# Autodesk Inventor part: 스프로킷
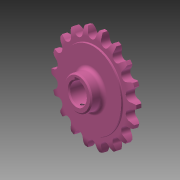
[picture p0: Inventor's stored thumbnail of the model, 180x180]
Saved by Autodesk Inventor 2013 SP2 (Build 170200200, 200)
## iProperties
Created: 2016-03
Part Number: 스프로킷
Material: 강철, 탄소
Document SubType Name: Modeling
Designer: mduedu
Density: 7.87 g/cm^3
Mass: 301.818 g
Surface Area: 124.882 cm^2
Volume: 38.3505 cm^3
Author: mduedu
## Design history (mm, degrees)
sketch "스케치1"
  geometry: L1 (0, 5)-(29.5, 5); L2 (29.5, 5)-(29.5, 4.1); L3 (30, 3.6)-(33.625, 3.6); L4 (40, 2)-(40, 0); L5 (40, 0)-(0, 0); L6 (0, 0)-(0, 5); L7 (0, -5)-(29.5, -5); L8 (29.5, -5)-(29.5, -4.1); L9 (30, -3.6)-(33.625, -3.6); L10 (40, -2)-(40, 0); L11 (0, 0)-(0, -5); A1 r 13.5 centre (33.625, -9.9) between (40, 2) and (33.625, 3.6); A2 r 13.5 centre (33.625, 9.9) between (33.625, -3.6) and (40, -2); A3 r 0.5 centre (30, 4.1) between (29.5, 4.1) and (30, 3.6); A4 r 0.5 centre (30, -4.1) between (30, -3.6) and (29.5, -4.1); 2 further points
  constraints: 22 end point, 8 point on circle, 6 symmetric about line, 5 tangent, 4 centre point, 4 parallel, 4 point on line, 1 equal radius, 1 horizontal, 1 perpendicular, 1 other
  dimensions: "d0" = 80 diameter of L4 L6; "d2" = 59 diameter of L2 L6; "d3" = 1.6 vertical distance of L4.start L3.end; "d4" = 3.6 distance from line of L4.end L3; "d5" = 5 distance between parallel lines of L5 L1; "d6" = 13.5 radius of A1; "d15" = 0.5 radius of A3
revolve "회전1" sketch "스케치1" stored, may be unused: angle "d7" = 90 deg
sketch "스케치2" dims "d8" = 65.2, "d11" = 80
  geometry: L1 (0, 0)-(0, 32.6); A1 r 36.57 centre (0, 0) between (-16.231, 32.771) and (0, 36.57); A2 r 3.97 centre (0, 36.57) between (-3.866, 35.665) and (0, 32.6); A3 r 12.7 centre (-16.231, 32.771) between (-3.866, 35.665) and (-5.534, 39.615); A4 r 12.7 centre (16.231, 32.771) between (5.534, 39.615) and (3.866, 35.665); A5 r 3.97 centre (0, 36.57) between (0, 32.6) and (3.866, 35.665); A6 r 40 centre (0, 0) between (5.534, 39.615) and (-5.534, 39.615); 2 further points
  constraints: 12 point on circle, 6 centre point, 4 coincident, 3 symmetric about line, 2 end point, 1 point on line, 1 tangent, 1 vertical, 1 vertical alignment, 7 other
  dimensions: "d10" = 73.14 diameter of A1; "d12" = 12.7 radius of A3
extrude "돌출1" cut sketch "스케치2" stored distance "d13" = 10; taper "d14" = 0 deg
sketch "스케치3"
  geometry: C1 r 13 at (0, 0); 1 further point
  constraints: 1 centre point, 1 coincident
  dimensions: "d19" = 26 diameter of C1
extrude "돌출2" join sketch "스케치3" distance "d20" = 10; taper "d21" = 0 deg
fillet "모깎기1" dims "d22" = 3
sketch "스케치4"
  geometry: L1 (-2.5, 0)-(2.5, 0); L2 (2.5, 0)-(2.5, 10.3); L3 (2.5, 10.3)-(-2.5, 10.3); L4 (-2.5, 10.3)-(-2.5, 0); C1 r 8 at (0, 0); 2 further points
  constraints: 8 end point, 2 coincident, 2 parallel, 1 centre point, 1 horizontal, 1 midpoint, 1 perpendicular
  dimensions: "d23" = 16 diameter of C1; "d25" = 5 distance of L2.end L3.end; "d26" = 10.3 distance of L1.end L2.end
extrude "돌출3" cut sketch "스케치4" stored distance "d27" = 8; taper "d28" = 0 deg
chamfer "모따기2" distance "d42" = 1; stored, may be unused: second distance "d43" = 2, angle "d44" = 45 deg
node "작업 평면2"
sketch "스케치6"
  geometry: L1 (-12, 15)-(12, 15) reference; 2 further points
  constraints: 1 vertical alignment
  dimensions: "d59" = 4 distance from line of point (0.008, 11) L1
hole "구멍2" sketch "스케치6" at (0.008, 11) diameter "d48" = 3; stored, may be unused: countersink angle "d52" = 90 deg, drill point angle "d54" = 118 deg; dims "d49" = 6, "d50" = 4, "d51" = 2, "d53" = 8
thread "Thread1" dims "d56" = 10, "d57" = 0
node "솔리드1"
pattern_circular "원형 패턴1" dims angle "d17" = 360 deg
other parameters: "d55" = -13
